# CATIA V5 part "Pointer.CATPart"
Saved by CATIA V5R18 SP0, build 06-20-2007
Part number: Part2
Bounding box of the stored display mesh (mm): x -12.875 to 12.875, y -12.732 to 12.732, z 0 to 100
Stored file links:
  D:\shriniwas\v5_r19\c16_CAT_v5r19\c16_Part\Point Surface Joint\Pointer.CATPart
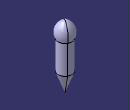
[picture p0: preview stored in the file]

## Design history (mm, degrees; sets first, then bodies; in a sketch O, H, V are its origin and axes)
Body1 (main body)
  Sketch1 on yz-plane, origin (0, 0, 0), H (0, 1, 0), V (0, 0, 1)
    line L1 (0, 0) -> (10.9446, 30.0702)
    point P1 (10.9446, 30.0702)
    line L2 (10.9446, 30.0702) -> (10.9446, 75.0702)
    point P2 (10.9446, 30.0702)
    point P3 (10.9446, 75.0702)
    arc A1 centre (-4.3336, 83.2301) radius 17.3208 from (10.9446, 75.0702) to (0, 100) ccw
    point P5 (0, 100)
    point P6 (10.9446, 91.3901)
    line L3 (0, 0) -> (0, 100)
    reference intersected line E1 through (0, 0) direction (-1, 0) from xy-plane
    reference intersected line E3 through (0, 0) direction (0, 1) from zx-plane
    radius A1 = 17.3208
    angle L1 L3 = 20
    distance O P1 = 32
    distance O P5 = 100
    distance P2 P3 = 45
    coincidence: P2 L1, P5 V, A1 P6, P6 L2, P2 P1, E3 P5, P1 L2
    vertical: L2 V, L3 V, E3 V
    horizontal: E1 H
    perpendicularity: E1 L2
  Shaft1: profile Sketch1, axis Sketch1.L3, angle 360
